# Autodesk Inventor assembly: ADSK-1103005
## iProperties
Created: 2006-01
Part Number: ADSK-1103005
Document SubType Name: Assembly
Manufacturer: Standard
Standards Organization: Custom
Weld Material: Default
Description: ENGINE CASE
Mass: 4.10148 g
Surface Area: 56.5229 cm^2
Volume: 1.52675 cm^3
Density: 2.6864 g/cm^3
Designer: Autodesk, Inc.
Title: Rear Exhaust Manifold
Author: Autodesk, Inc.
